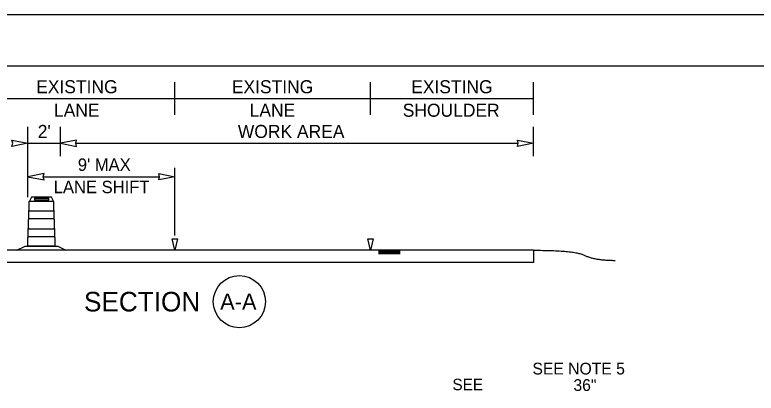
# Model space of a CAD drawing. Extents: x 99999 to 100116, y 99995 to 100013.
# Drawn here: x 100026.677 to 100031.224, y 100008.369 to 100010.687 of the extents above; entities that cross this region are included whole.
import ezdxf

# ---------------------------------------------------------------- set-up
doc = ezdxf.new("R2010")
doc.units = 0
for name, color, linetype in [('SH_GI_PlotLimits', 7, 'Continuous'), ('SH_GI_SheetBorder', 7, 'Continuous'), ('SH_TI_WZSectionCut', 7, 'Continuous'), ('TR_SN_ConstructionSigns', 7, 'Continuous'), ('TR_WZ_TrafficSafetyDrumElev', 7, 'Continuous')]:
    doc.layers.add(name, color=color, linetype=linetype)

msp = doc.modelspace()

# ---------------------------------------------------------------- linework, layer by layer
at = {"layer": 'SH_GI_PlotLimits'}
msp.add_lwpolyline([(100019.0625, 99999.6875), (100036.0625, 99999.6875), (100036.0625, 100010.6875), (100019.0625, 100010.6875)], close=True, dxfattribs=at)
at = {"layer": 'SH_GI_SheetBorder'}
msp.add_line((100020, 100010.375), (100035.75, 100010.375), dxfattribs=at)
at = {"layer": 'SH_TI_WZSectionCut'}
for p, q in [((100027.6578, 100010.075), (100027.6578, 100010.275)), ((100028.8578, 100010.075), (100028.8578, 100010.275)), ((100029.8578, 100010.075), (100029.8578, 100010.275)), ((100026.4578, 100010.175), (100027.6578, 100010.175)), ((100027.6578, 100010.175), (100028.8578, 100010.175)), ((100028.8578, 100010.175), (100029.8578, 100010.175)), ((100026.7578, 100009.57), (100026.7578, 100010.001)), ((100026.9578, 100009.821), (100026.9578, 100010.001)), ((100029.8578, 100009.821), (100029.8578, 100010.001)), ((100026.7578, 100009.901), (100026.9578, 100009.901)), ((100027.0515, 100009.901), (100029.764, 100009.901)), ((100027.6578, 100009.3347), (100027.6578, 100009.75)), ((100026.8515, 100009.6955), (100027.564, 100009.6955)), ((100029.8578, 100009.2449), (100025.4578, 100009.2449)), ((100029.0408, 100009.2393), (100028.9078, 100009.2393)), ((100029.0408, 100009.2337), (100028.9078, 100009.2337)), ((100029.0408, 100009.228), (100028.9078, 100009.228)), ((100029.0408, 100009.2228), (100028.9078, 100009.2228)), ((100029.8578, 100009.2449), (100029.8578, 100009.1699)), ((100029.8578, 100009.1699), (100025.4578, 100009.1699))]:
    msp.add_line(p, q, dxfattribs=at)
for points in [[(100026.7578, 100009.901), (100026.6595, 100009.8817), (100026.664, 100009.901), (100026.6595, 100009.9203)], [(100026.9578, 100009.901), (100027.056, 100009.8817), (100027.0515, 100009.901), (100027.056, 100009.9203)], [(100029.8578, 100009.901), (100029.7595, 100009.8817), (100029.764, 100009.901), (100029.7595, 100009.9203)], [(100026.7578, 100009.6955), (100026.856, 100009.6762), (100026.8515, 100009.6955), (100026.856, 100009.7148)], [(100027.6578, 100009.6955), (100027.5595, 100009.6762), (100027.564, 100009.6955), (100027.5595, 100009.7148)], [(100027.6411, 100009.3147), (100027.6744, 100009.3147), (100027.6578, 100009.2449)], [(100028.8411, 100009.3147), (100028.8744, 100009.3147), (100028.8578, 100009.2449)]]:
    msp.add_lwpolyline(points, close=True, dxfattribs=at)
msp.add_circle((100028.0543, 100008.93), 0.16, dxfattribs=at)
msp.add_open_spline([(100029.8578, 100009.2449), (100030.1089, 100009.2451), (100030.2344, 100009.183), (100030.3599, 100009.1831)], degree=2, dxfattribs=at)
at = {"layer": 'TR_WZ_TrafficSafetyDrumElev'}
for p, q in [((100026.7661, 100009.545), (100026.9141, 100009.545)), ((100026.7661, 100009.545), (100026.9141, 100009.545)), ((100026.8006, 100009.564), (100026.8824, 100009.564)), ((100026.8824, 100009.551), (100026.8006, 100009.551)), ((100026.7633, 100009.4871), (100026.917, 100009.4871)), ((100026.7633, 100009.4372), (100026.7633, 100009.4871)), ((100026.917, 100009.4871), (100026.917, 100009.4372)), ((100026.917, 100009.4372), (100026.7633, 100009.4372)), ((100026.7596, 100009.377), (100026.9207, 100009.377)), ((100026.7596, 100009.3271), (100026.7596, 100009.377)), ((100026.9207, 100009.377), (100026.9207, 100009.3271)), ((100026.9207, 100009.3271), (100026.7596, 100009.3271))]:
    msp.add_line(p, q, dxfattribs=at)
for points in [[(100026.7651, 100009.4915), (100026.7651, 100009.543)], [(100026.7651, 100009.4915), (100026.7651, 100009.543)], [(100026.9151, 100009.543), (100026.9151, 100009.4915)], [(100026.9151, 100009.543), (100026.9151, 100009.4915)], [(100026.7633, 100009.4365), (100026.7633, 100009.4878)], [(100026.7633, 100009.4365), (100026.7633, 100009.4878)], [(100026.917, 100009.4878), (100026.917, 100009.4365)], [(100026.917, 100009.4878), (100026.917, 100009.4365)], [(100026.7614, 100009.3814), (100026.7614, 100009.4327)], [(100026.7614, 100009.3814), (100026.7614, 100009.4327)], [(100026.9188, 100009.4327), (100026.9188, 100009.3814)], [(100026.9188, 100009.4327), (100026.9188, 100009.3814)], [(100026.7596, 100009.3264), (100026.7596, 100009.3777)], [(100026.7596, 100009.3264), (100026.7596, 100009.3777)], [(100026.9207, 100009.3777), (100026.9207, 100009.3264)], [(100026.9207, 100009.3777), (100026.9207, 100009.3264)], [(100026.9225, 100009.3226), (100026.9225, 100009.27), (100026.7578, 100009.27), (100026.7578, 100009.3226)], [(100026.9225, 100009.3226), (100026.9225, 100009.27), (100026.7578, 100009.27), (100026.7578, 100009.3226)]]:
    msp.add_lwpolyline(points, dxfattribs=at)
for points in [[(100026.9141, 100009.545), (100026.901, 100009.57), (100026.7793, 100009.57), (100026.7661, 100009.545)], [(100026.6901, 100009.245), (100026.7404, 100009.27), (100026.9399, 100009.27), (100026.9901, 100009.245)]]:
    msp.add_lwpolyline(points, close=True, dxfattribs=at)
for centre, major_axis, ratio, start_param, end_param in [((100026.7664, 100009.5426), (0, 0.00249), 0.493438, 0.177149, 1.393647), ((100026.7664, 100009.5426), (0, 0.00249), 0.493438, 0.177149, 1.393647), ((100026.8006, 100009.5575), (0, 0.0065), 0.570305, 0, 3.141593), ((100026.8824, 100009.5575), (0, 0.0065), 0.570305, 3.141593, 6.283185), ((100026.9139, 100009.5426), (0, 0.00249), 0.493438, 4.889538, 6.106036), ((100026.9139, 100009.5426), (0, 0.00249), 0.493438, 4.889538, 6.106036), ((100026.7667, 100009.4846), (0, 0.00758), 0.493438, 0.4288, 1.141997), ((100026.7667, 100009.4846), (0, 0.00758), 0.493438, 0.4288, 1.141997), ((100026.9136, 100009.4846), (0, 0.00758), 0.493438, 5.141189, 5.854386), ((100026.9136, 100009.4846), (0, 0.00758), 0.493438, 5.141189, 5.854386), ((100026.7648, 100009.4296), (0, 0.00758), 0.493438, 0.4288, 1.141997), ((100026.7648, 100009.4296), (0, 0.00758), 0.493438, 0.4288, 1.141997), ((100026.9154, 100009.4296), (0, 0.00758), 0.493438, 5.141189, 5.854386), ((100026.9154, 100009.4296), (0, 0.00758), 0.493438, 5.141189, 5.854386), ((100026.763, 100009.3745), (0, 0.00758), 0.493438, 0.4288, 1.141997), ((100026.763, 100009.3745), (0, 0.00758), 0.493438, 0.4288, 1.141997), ((100026.9173, 100009.3745), (0, 0.00758), 0.493438, 5.141189, 5.854386), ((100026.9173, 100009.3745), (0, 0.00758), 0.493438, 5.141189, 5.854386), ((100026.7612, 100009.3195), (0, 0.00758), 0.493438, 0.4288, 1.141997), ((100026.7612, 100009.3195), (0, 0.00758), 0.493438, 0.4288, 1.141997), ((100026.9191, 100009.3195), (0, 0.00758), 0.493438, 5.141189, 5.854386), ((100026.9191, 100009.3195), (0, 0.00758), 0.493438, 5.141189, 5.854386)]:
    msp.add_ellipse(centre, major_axis=major_axis, ratio=ratio, start_param=start_param, end_param=end_param, dxfattribs=at)

# ---------------------------------------------------------------- texts
at = {"layer": 'SH_TI_WZSectionCut'}
for s, height, p in [('EXISTING', 0.08, (100026.808, 100010.207)), ('EXISTING', 0.08, (100028.008, 100010.207)), ('EXISTING', 0.08, (100029.108, 100010.207)), ('LANE', 0.08, (100026.9174, 100010.063)), ('LANE', 0.08, (100028.1174, 100010.063)), ('SHOULDER', 0.08, (100029.056, 100010.063)), ('SECTION', 0.12, (100027.1012, 100008.87)), ('A-A', 0.1, (100027.9364, 100008.88))]:
    msp.add_text(s, height=height, rotation=360, dxfattribs=at).set_placement(p)
for s, height, p in [("2'", 0.08, (100026.8177, 100009.933)), ('WORK AREA', 0.08, (100028.0449, 100009.933)), ("9' MAX", 0.076, (100027.0635, 100009.7315)), ('LANE SHIFT', 0.076, (100026.9157, 100009.5947))]:
    msp.add_text(s, height=height, dxfattribs=at).set_placement(p)
at = {"layer": 'TR_SN_ConstructionSigns'}
for s, height, p in [('SEE NOTE 5', 0.072, (100029.8515, 100008.4838)), ('SEE', 0.07, (100029.3611, 100008.3877)), ('36"', 0.072, (100030.103, 100008.383))]:
    msp.add_text(s, height=height, rotation=360, dxfattribs=at).set_placement(p)

doc.saveas('drawing.dxf')
